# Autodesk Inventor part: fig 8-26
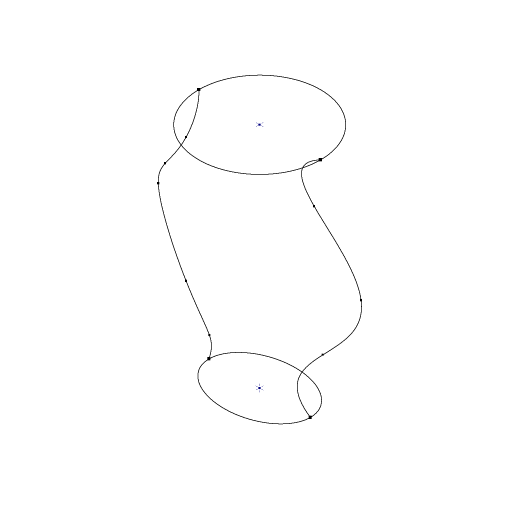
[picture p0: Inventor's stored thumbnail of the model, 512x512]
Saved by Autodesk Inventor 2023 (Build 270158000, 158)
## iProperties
Part Number: fig 8-26
Document SubType Name: Modeling
Created: 2002-12
Designer: deepak
Density: 1 g/cm^3
Material: Generic
Appearance: Default
Control State: 0
Master: False
Checked Out: False
Shininess: 64.0
Length Units: 11269
Angle Units: 11279
Time Units: 11290
Mass Units: 11283
Length Display Precision: 3
Angle Display Precision: 2
Compacted: True
Density: 0.0
Volumn: 0.0
Area: 0.0
PropertySet Name: Model Information
Author: deepak
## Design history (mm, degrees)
sketch "Sketch1"
  geometry: 2 further points; 1 other entity
  constraints: 1 coincident, 3 other
workplane "Work Plane1"
workplane "Work Plane2"
sketch "Sketch3"
  geometry: C1 r 60 at (0, 0); 1 further point
  constraints: 1 centre point, 1 coincident, 1 other
sketch "Sketch4"
  geometry: 8 further points
  constraints: 8 other
sketch "Sketch5"
  geometry: 6 further points
  constraints: 6 other
sketch "Sketch6"
  geometry: 6 further points
  constraints: 6 other
  dimensions: "d20" = 35 distance of point (0, 0) point (-35, 0); "d21" = 0 vertical distance of point (0, 0) point (-35, 0); "d22" = 225 vertical distance of point (0, 0) point (-60, 225); "d23" = 60 horizontal distance of point (0, 0) point (-60, 225); "d24" = 100 horizontal distance of point (0, 0) point (-100, 125); "d25" = 125 vertical distance of point (0, 0) point (-100, 125)
other parameters: "d5" = 125
